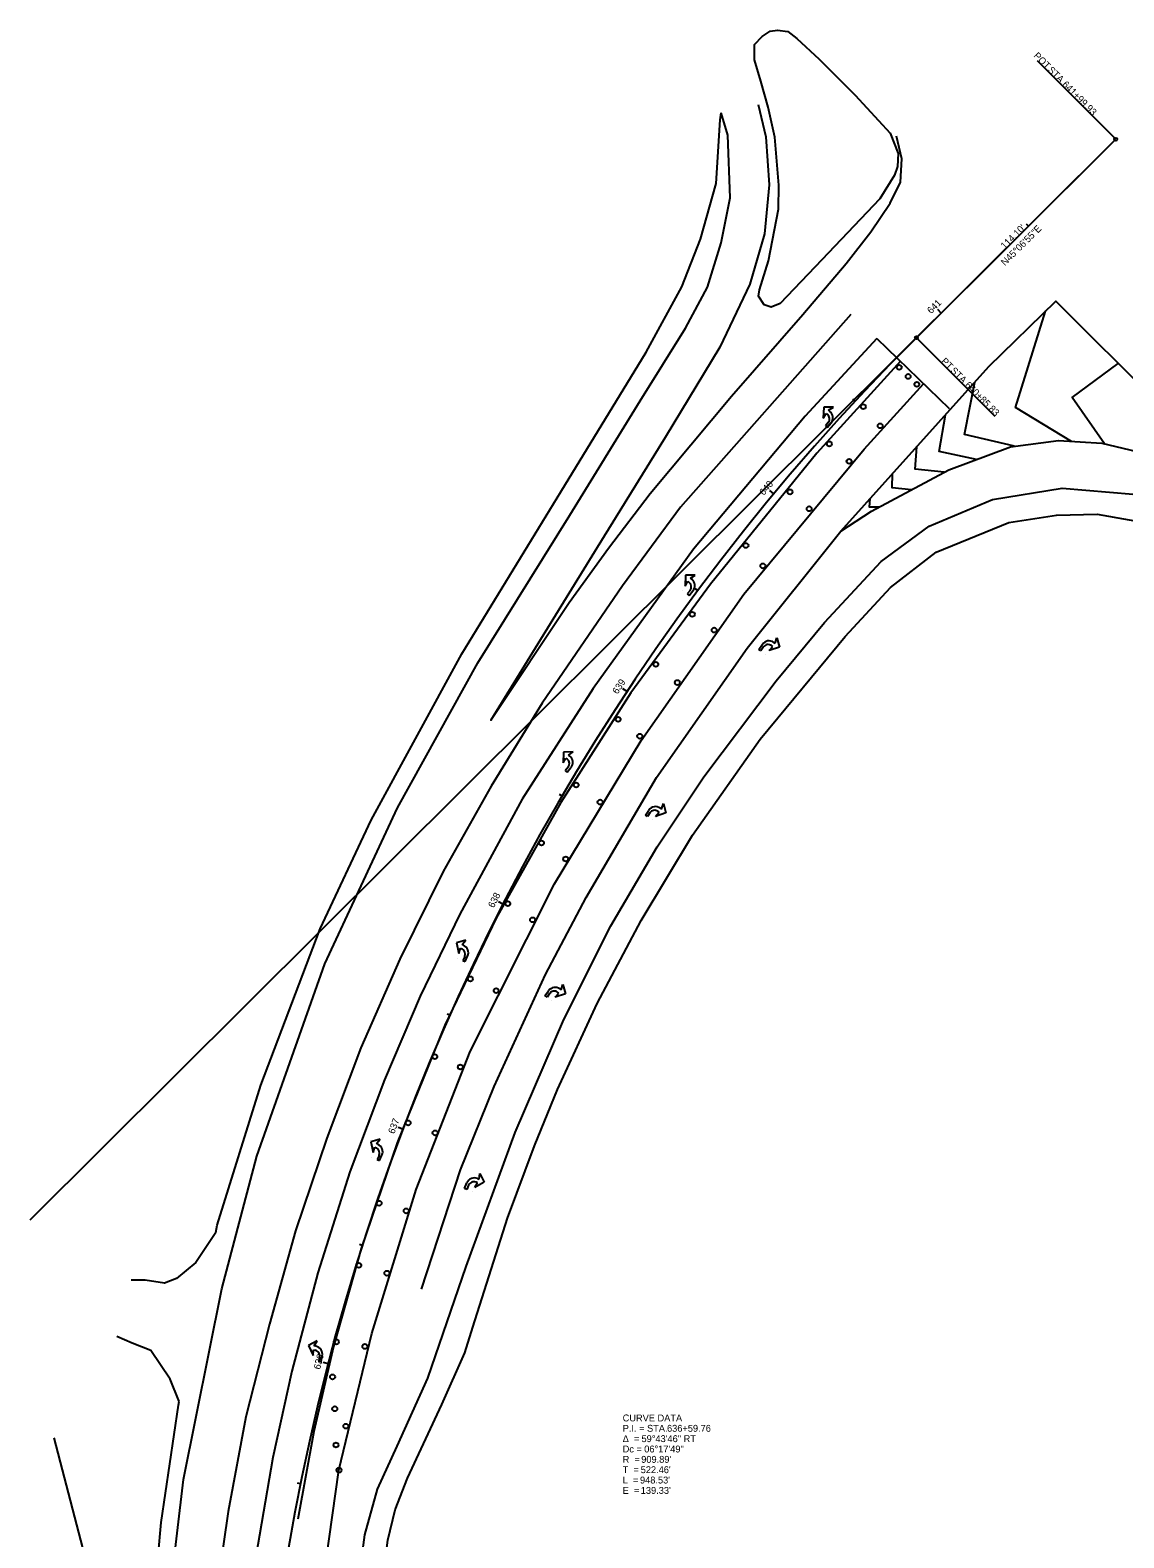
# Model space of a CAD drawing. Extents: x 171274 to 172251, y 454256 to 458569.
# Drawn here: x 171274 to 171718, y 456216 to 456829 of the extents above; entities that cross this region are included whole.
import ezdxf

# ---------------------------------------------------------------- set-up
doc = ezdxf.new("R2010")
doc.units = 0
for name, color, linetype in [('_CIVIL_CONSTRUCTION', 7, 'Continuous'), ('BR_P_Gen_Waterproofing', 7, 'Continuous'), ('BR_X_Beam_Hidden', 7, 'Continuous'), ('BR_X_Brg_Pad_Object', 7, 'Continuous'), ('BR_X_Gen_Approach_Slab', 7, 'Continuous'), ('BR_X_Rail_Object', 7, 'Continuous'), ('BR_X_Sub_Backwall', 7, 'Continuous'), ('PV_P_Saw_Cut_Line', 7, 'Continuous'), ('PV_X_Saw_Cut_Line', 7, 'Continuous'), ('PV_X_Walk', 7, 'Continuous'), ('SC_Scratch2', 7, 'Continuous'), ('SC_Scratch3', 7, 'Continuous'), ('SC_Scratch4', 7, 'Continuous'), ('UT_X_Water_Cells', 7, 'Continuous'), ('VG_X_Cells', 7, 'Continuous'), ('VG_X_Shrub_Line_Lt', 7, 'Continuous'), ('VG_X_Shrub_Line_Rt', 7, 'Continuous')]:
    doc.layers.add(name, color=color, linetype=linetype)

msp = doc.modelspace()

# ---------------------------------------------------------------- linework, layer by layer
at = {"layer": '_CIVIL_CONSTRUCTION'}
for p, q in [((171273.99, 456345.54), (171714.41, 456784.19)), ((171633.56, 456703.67), (171714.41, 456784.19)), ((171701.51, 454654.7), (171283.69, 456257.09))]:
    msp.add_line(p, q, dxfattribs=at)
msp.add_arc((172275.65, 456058.99), 909.89, 134.88472, 194.61425, dxfattribs=at)
msp.add_arc((172275.65, 456058.99), 909.89, 134.88472, 194.61425, dxfattribs=at)
at = {"layer": 'BR_X_Beam_Hidden'}
for points in [[(171569.33, 456798.27), (171572.44, 456785.16), (171573.8, 456765.69), (171571.94, 456745.78), (171566.04, 456725.39), (171553.76, 456699.87), (171531.66, 456663.16), (171504, 456618.55), (171460.9, 456548.38), (171492.68, 456596.2), (171508.69, 456618.21), (171525.54, 456640.38), (171558.59, 456679.98), (171587.53, 456713.13), (171605.13, 456733.84), (171615.03, 456746.64), (171622.89, 456758.28), (171627.16, 456766.82), (171627.64, 456776.24), (171625.47, 456785.54)], [(171602.92, 456625.18), (171663.01, 456692.03), (171690.1, 456718.51), (171772.11, 456636.73)], [(171627.06, 456694.1), (171593.23, 456656.78), (171550, 456603.64), (171517.74, 456559.5), (171489.28, 456515.03), (171463.11, 456468.03), (171442.22, 456424.53), (171422.9, 456376.79), (171408.32, 456333.98), (171397.11, 456294.2), (171389.07, 456259.62), (171382.57, 456224.06)], [(171432.73, 456317.37), (171448.55, 456365.88), (171462.25, 456399.72), (171483.02, 456445.22), (171499.61, 456476.41), (171528.05, 456525.13), (171564.96, 456577.65), (171602.92, 456625.18), (171615.36, 456633.22), (171646.74, 456650.07), (171671.8, 456659.37), (171691.22, 456661.9), (171708.76, 456660.87), (171728.62, 456656.06), (171746.7, 456650.15), (171767.78, 456639.28), (171772.11, 456636.73), (171794.37, 456614.66), (171830.07, 456578.67)]]:
    msp.add_lwpolyline(points, dxfattribs=at)
at = {"layer": 'BR_X_Brg_Pad_Object'}
for points in [[(171327.94, 456170.26), (171336.25, 456240.13), (171351.77, 456317.57), (171365.9, 456371.47), (171393.58, 456449.55), (171423.04, 456512.85), (171455.59, 456571.64), (171492.97, 456631.68), (171521.52, 456678.08), (171539.93, 456707.53), (171548.77, 456724.18), (171554.3, 456742.14), (171557.95, 456760.43), (171557.04, 456785.92), (171554.4, 456794.89)], [(171402.37, 456161.63), (171409.79, 456217.67), (171414.9, 456236.24), (171422.84, 456253.76), (171435.4, 456281.25), (171450.83, 456326.64), (171470.71, 456380.98), (171490.47, 456426.83), (171509.54, 456464.85), (171528.44, 456497.04), (171547.35, 456525.34), (171576.69, 456564.34), (171596.21, 456588.1), (171619.26, 456612.82), (171638.68, 456627.21), (171664.37, 456638), (171692.67, 456642.65), (171721.46, 456640.13), (171751.65, 456628.68), (171774.21, 456614.17), (171819.99, 456570.17)]]:
    msp.add_lwpolyline(points, dxfattribs=at)
at = {"layer": 'BR_X_Gen_Approach_Slab'}
msp.add_lwpolyline([(171617.49, 456703.32), (171588.41, 456671.87), (171543.08, 456617.86), (171502.42, 456561.24), (171473.6, 456516.31), (171448.38, 456469.66), (171432.22, 456436.4), (171417.81, 456402.4), (171403.7, 456365.07), (171390.74, 456323.99), (171380.22, 456284.08), (171372.41, 456249.06), (171365.59, 456208.9)], dxfattribs=at)
at = {"layer": 'BR_X_Rail_Object'}
for centre in [(171626.59, 456691.62), (171630.23, 456687.93), (171633.74, 456684.73), (171612, 456675.67), (171618.87, 456667.89), (171598.23, 456660.55), (171606.25, 456653.48), (171582.3, 456641.06), (171590.06, 456634.23), (171564.39, 456619.3), (171571.29, 456611.02), (171542.62, 456591.39), (171551.51, 456584.96), (171527.84, 456571.07), (171536.56, 456563.67), (171512.54, 456548.76), (171521.33, 456541.89), (171495.5, 456522.09), (171505.23, 456515.15), (171481.45, 456498.56), (171491.28, 456492.06), (171467.79, 456473.9), (171477.84, 456467.35), (171452.58, 456443.37), (171463.09, 456438.6), (171438.14, 456411.82), (171448.51, 456407.62), (171427.34, 456384.92), (171438.28, 456380.87), (171415.55, 456352.3), (171426.56, 456349.2), (171407.3, 456327.09), (171418.74, 456323.9), (171398.2, 456296.01), (171409.8, 456294.19), (171396.68, 456281.82), (171397.58, 456268.88), (171402.07, 456261.81), (171398.06, 456254.18), (171399.27, 456243.93)]:
    msp.add_circle(centre, 1, dxfattribs=at)
at = {"layer": 'BR_X_Sub_Backwall'}
msp.add_lwpolyline([(171399.27, 456243.93), (171412.62, 456299.43), (171430.57, 456357.84), (171452.53, 456413.92), (171486.74, 456481.97), (171521.83, 456540.12), (171563.53, 456599.56), (171612.4, 456658.42), (171636.48, 456684.91)], dxfattribs=at)
at = {"layer": 'PV_P_Saw_Cut_Line'}
msp.add_lwpolyline([(171624.65, 456769.69), (171618.76, 456760.02), (171595.18, 456735.32), (171578.31, 456717.51), (171574.63, 456716.11), (171571.85, 456717.07), (171569.46, 456720.5), (171569.93, 456723.14), (171573.55, 456734.86), (171577.66, 456755.81), (171577.69, 456765.63), (171576.16, 456785.11), (171573.37, 456797.29), (171570.45, 456807.76), (171567.85, 456816.44), (171567.93, 456822.67), (171570.95, 456825.94), (171574.17, 456828.08), (171577.25, 456828.51), (171581.38, 456827.94), (171585.04, 456825.14), (171594.17, 456816.74), (171608.72, 456802.09), (171622.85, 456786.66), (171626.11, 456778.44), (171625.91, 456773.15)], close=True, dxfattribs=at)
for points in [[(171349.3, 456340.43), (171349.93, 456343.34), (171367.6, 456400.19), (171391.6, 456463.7), (171412.29, 456507.8), (171449.08, 456575.38), (171489.26, 456641.12), (171523.9, 456697.76), (171538.43, 456724.37), (171545.99, 456743.73), (171552.35, 456766.31), (171553.97, 456792.06), (171554.4, 456794.89)], [(171478.59, 456375.6), (171487.98, 456398.43), (171504.03, 456433.44), (171521.95, 456467.05), (171542.72, 456501.75), (171570.11, 456540.74), (171604.7, 456582.33), (171622.99, 456602.24), (171641.52, 456616.62), (171671.01, 456628.7), (171690.37, 456631.59), (171706.84, 456631.97), (171730.61, 456627.89), (171744.29, 456622.3), (171760.51, 456613.41), (171776.5, 456599.81), (171809.32, 456567.8)], [(171461.92, 455723.14), (171461.11, 455726.64), (171445.31, 455796.47), (171431.02, 455865.63), (171421.47, 455918.95), (171413.26, 455981.96), (171409.27, 456040.86), (171408.32, 456093.56), (171412.13, 456160.37), (171419.13, 456215.58), (171422.03, 456227.81), (171427.08, 456240.66), (171441.08, 456270.63), (171450.32, 456291.63), (171453.6, 456301.97), (171467.65, 456346.3), (171478.59, 456375.6)], [(171558.29, 455107.46), (171557.48, 455110.64), (171540.93, 455172.92), (171510.71, 455286.81), (171486.61, 455378.45), (171470.46, 455441.39), (171454.22, 455507.71), (171429.71, 455601.02), (171414.88, 455651.31), (171387.7, 455745.41), (171360.93, 455847.8), (171341.64, 455927.77), (171327.71, 456008.91), (171320.5, 456092.02), (171319.84, 456141.55), (171327.18, 456222.76), (171334.15, 456270.38), (171334.45, 456271.77)]]:
    msp.add_lwpolyline(points, dxfattribs=at)
at = {"layer": 'PV_X_Saw_Cut_Line'}
for p, q in [((171599.89, 456675.51), (171595.94, 456675.42)), ((171597.96, 456674.19), (171599.89, 456675.51)), ((171599.89, 456675.51), (171599.89, 456675.51)), ((171595.94, 456675.42), (171595.79, 456671)), ((171595.79, 456671), (171596.95, 456672.95)), ((171596.95, 456672.95), (171597.49, 456672.51)), ((171598.47, 456673.77), (171597.96, 456674.19)), ((171594.83, 456669.3), (171594.83, 456669.3)), ((171597.82, 456669.27), (171596.64, 456667.83)), ((171596.64, 456667.83), (171597.42, 456667.2)), ((171597.42, 456667.2), (171598.98, 456669.12)), ((171539.85, 456607.24), (171539.69, 456602.83)), ((171539.69, 456602.83), (171540.85, 456604.78)), ((171543.79, 456607.33), (171539.85, 456607.24)), ((171540.85, 456604.78), (171541.4, 456604.33)), ((171541.86, 456606.02), (171543.79, 456607.33)), ((171542.38, 456605.6), (171541.86, 456606.02)), ((171543.79, 456607.33), (171543.79, 456607.33)), ((171538.74, 456601.13), (171538.74, 456601.13)), ((171541.73, 456601.1), (171540.55, 456599.66)), ((171540.55, 456599.66), (171541.32, 456599.03)), ((171541.32, 456599.03), (171542.89, 456600.95)), ((171569.66, 456577.15), (171571.07, 456579.19)), ((171571.54, 456578.11), (171570.48, 456576.58)), ((171573.76, 456576.64), (171575.31, 456578.29)), ((171577.96, 456578.01), (171573.76, 456576.64)), ((171575.31, 456578.29), (171574.74, 456578.69)), ((171575.68, 456579.98), (171576.23, 456579.6)), ((171576.23, 456579.6), (171576.96, 456581.82)), ((171576.96, 456581.82), (171576.96, 456581.82)), ((171576.96, 456581.82), (171577.96, 456578.01)), ((171570.48, 456576.58), (171569.66, 456577.15)), ((171572.4, 456575.25), (171572.4, 456575.25)), ((171490.38, 456535.47), (171490.23, 456531.06)), ((171494.33, 456535.56), (171490.38, 456535.47)), ((171492.39, 456534.24), (171494.33, 456535.56)), ((171494.33, 456535.56), (171494.33, 456535.56)), ((171489.27, 456529.36), (171489.27, 456529.36)), ((171490.23, 456531.06), (171491.38, 456533)), ((171492.26, 456529.33), (171491.08, 456527.88)), ((171491.38, 456533), (171491.93, 456532.56)), ((171491.86, 456527.25), (171493.42, 456529.17)), ((171492.91, 456533.82), (171492.39, 456534.24)), ((171491.08, 456527.88), (171491.86, 456527.25)), ((171523.59, 456509.87), (171525, 456511.9)), ((171525.47, 456510.83), (171524.41, 456509.3)), ((171527.7, 456509.36), (171529.25, 456511.01)), ((171531.89, 456510.73), (171527.7, 456509.36)), ((171529.25, 456511.01), (171528.67, 456511.41)), ((171529.61, 456512.7), (171530.16, 456512.32)), ((171530.16, 456512.32), (171530.89, 456514.54)), ((171530.89, 456514.54), (171530.89, 456514.54)), ((171530.89, 456514.54), (171531.89, 456510.73)), ((171524.41, 456509.3), (171523.59, 456509.87)), ((171526.33, 456507.97), (171526.33, 456507.97)), ((171450.79, 456459.07), (171446.99, 456458.01)), ((171446.99, 456458.01), (171447.93, 456453.69)), ((171447.93, 456453.69), (171448.57, 456455.86)), ((171448.57, 456455.86), (171449.2, 456455.57)), ((171449.24, 456457.31), (171450.79, 456459.07)), ((171449.85, 456457.03), (171449.24, 456457.31)), ((171450.79, 456459.07), (171450.79, 456459.07)), ((171447.42, 456451.81), (171447.42, 456451.81)), ((171450.32, 456452.52), (171449.54, 456450.83)), ((171449.54, 456450.83), (171450.44, 456450.41)), ((171450.44, 456450.41), (171451.49, 456452.65)), ((171482.87, 456436.48), (171484.28, 456438.51)), ((171484.75, 456437.44), (171483.69, 456435.91)), ((171486.97, 456435.96), (171488.52, 456437.62)), ((171491.17, 456437.34), (171486.97, 456435.96)), ((171488.52, 456437.62), (171487.95, 456438.02)), ((171488.89, 456439.31), (171489.44, 456438.93)), ((171489.44, 456438.93), (171490.16, 456441.15)), ((171490.16, 456441.15), (171490.16, 456441.15)), ((171490.16, 456441.15), (171491.17, 456437.34)), ((171483.69, 456435.91), (171482.87, 456436.48)), ((171485.61, 456434.58), (171485.61, 456434.58)), ((171416.03, 456378.25), (171412.23, 456377.19)), ((171412.23, 456377.19), (171413.17, 456372.88)), ((171414.48, 456376.5), (171416.03, 456378.25)), ((171415.09, 456376.22), (171414.48, 456376.5)), ((171416.03, 456378.25), (171416.03, 456378.25)), ((171412.66, 456371), (171412.66, 456371)), ((171413.17, 456372.88), (171413.81, 456375.05)), ((171413.81, 456375.05), (171414.45, 456374.75)), ((171415.56, 456371.7), (171414.78, 456370.01)), ((171414.78, 456370.01), (171415.69, 456369.59)), ((171415.69, 456369.59), (171416.73, 456371.84)), ((171456.15, 456362.06), (171456.39, 456364.39)), ((171456.39, 456364.39), (171456.39, 456364.39)), ((171456.39, 456364.39), (171458.19, 456360.88)), ((171450.27, 456358.25), (171451.21, 456360.54)), ((171451.19, 456357.87), (171450.27, 456358.25)), ((171451.9, 456359.59), (171451.19, 456357.87)), ((171458.19, 456360.88), (171454.39, 456358.64)), ((171454.39, 456358.64), (171455.55, 456360.58)), ((171455.55, 456360.58), (171454.9, 456360.85)), ((171455.54, 456362.32), (171456.15, 456362.06)), ((171453.35, 456356.99), (171453.35, 456356.99)), ((171390.38, 456296.43), (171386.92, 456294.53)), ((171389.27, 456294.37), (171390.38, 456296.43)), ((171390.38, 456296.43), (171390.38, 456296.43)), ((171386.92, 456294.53), (171388.82, 456290.54)), ((171388.82, 456290.54), (171388.95, 456292.8)), ((171388.95, 456292.8), (171389.64, 456292.66)), ((171389.93, 456294.24), (171389.27, 456294.37)), ((171391.42, 456289.95), (171391.05, 456288.12)), ((171392.02, 456287.92), (171392.53, 456290.35)), ((171388.76, 456288.59), (171388.76, 456288.59)), ((171391.05, 456288.12), (171392.02, 456287.92))]:
    msp.add_line(p, q, dxfattribs=at)
for centre, radius, start, end in [((171596.04, 456670.72), 2.3, 320.82278, 50.82278), ((171596.44, 456671.19), 3.28, 320.82278, 51.73127), ((171539.95, 456602.55), 2.3, 320.82278, 50.82278), ((171540.35, 456603.02), 3.28, 320.82278, 51.73127), ((171573.77, 456577.32), 3.28, 54.35147, 145.25996), ((171573.43, 456576.8), 2.3, 55.25996, 145.25996), ((171490.48, 456530.78), 2.3, 320.82278, 50.82278), ((171490.88, 456531.25), 3.28, 320.82278, 51.73127), ((171527.7, 456510.03), 3.28, 54.35147, 145.25996), ((171527.36, 456509.52), 2.3, 55.25996, 145.25996), ((171448.24, 456453.48), 2.3, 335.10444, 65.10444), ((171448.51, 456454.04), 3.28, 335.10444, 66.01293), ((171486.98, 456436.64), 3.28, 54.35147, 145.25996), ((171486.64, 456436.13), 2.3, 55.25996, 145.25996), ((171413.75, 456373.22), 3.28, 335.10444, 66.01293), ((171413.48, 456372.67), 2.3, 335.10444, 65.10444), ((171454.25, 456359.3), 3.28, 66.81072, 157.71921), ((171454.03, 456358.72), 2.3, 67.71921, 157.71921), ((171389.17, 456290.41), 2.3, 348.31748, 78.31748), ((171389.31, 456291.01), 3.28, 348.31748, 79.22597)]:
    msp.add_arc(centre, radius, start, end, dxfattribs=at)
at = {"layer": 'PV_X_Walk'}
for points in [[(171696.51, 456661.59), (171673.71, 456675.32), (171685.94, 456714.43)], [(171709.89, 456660.6), (171696.82, 456679.36), (171715.44, 456693.24)], [(171673.36, 456659.57), (171653.08, 456664.33), (171657.25, 456685.62)], [(171657.97, 456654.24), (171642.81, 456657.44), (171645.3, 456672.32)], [(171644.88, 456649.07), (171633.08, 456650.29), (171633.7, 456659.42)], [(171631.52, 456641.9), (171623.73, 456642.72), (171623.92, 456648.54)], [(171618.47, 456634.89), (171614.56, 456634.82), (171614.79, 456638.39)]]:
    msp.add_lwpolyline(points, dxfattribs=at)
at = {"layer": 'SC_Scratch2'}
for points in [[(171606.9, 456713.08), (171537.84, 456634.83), (171514.38, 456602.92), (171481.72, 456555.36), (171461.08, 456521.63), (171441.58, 456486.99), (171424.04, 456451.38), (171408.15, 456415.38), (171394.36, 456378.7), (171381.63, 456341.12), (171371.07, 456303.24), (171361.56, 456265.59), (171354.26, 456227.23), (171348.62, 456187.8), (171344.87, 456148.4), (171343.42, 456109.47), (171343.88, 456070.6), (171348.16, 456014.58), (171355.27, 455960.53), (171369.03, 455890.22), (171386.9, 455814.22), (171470.04, 455501.07), (171508.5, 455352.39)], [(171472.94, 455579.79), (171449.73, 455676.12), (171434.2, 455742.49), (171417.65, 455817.01), (171409.54, 455855.66), (171396.62, 455926.7), (171388.55, 455991.19), (171385.59, 456030.86), (171384.04, 456092.24), (171385.52, 456132), (171388.97, 456170.87), (171399.27, 456243.93), (171412.62, 456299.43), (171430.57, 456357.84), (171452.53, 456413.92), (171486.74, 456481.97), (171521.83, 456540.12), (171563.53, 456599.56), (171612.4, 456658.42), (171636.48, 456684.91)]]:
    msp.add_lwpolyline(points, dxfattribs=at)
at = {"layer": 'SC_Scratch3'}
msp.add_line((171617.49, 456703.32), (171646.92, 456674.96), dxfattribs=at)
at = {"layer": 'SC_Scratch4'}
for p, q in [((171714.41, 456784.19), (171682.65, 456816.07)), ((171633.56, 456703.67), (171665.32, 456671.78))]:
    msp.add_line(p, q, dxfattribs=at)
for centre in [(171714.41, 456784.19), (171633.56, 456703.67)]:
    msp.add_circle(centre, 0.6, dxfattribs=at)
at = {"layer": 'UT_X_Water_Cells'}
for points in [[(171349.3, 456340.43), (171341.18, 456328.25), (171333.43, 456321.75), (171328.52, 456319.8), (171320.66, 456321.11), (171314.99, 456321.12)], [(171334.45, 456271.77), (171330.85, 456280.93), (171323, 456292.46), (171315.33, 456295.46), (171309.14, 456298.19)]]:
    msp.add_lwpolyline(points, dxfattribs=at)
at = {"layer": 'VG_X_Shrub_Line_Lt'}
for p, q in [((171679.03, 456748.95), (171678.18, 456749.8)), ((171643.6, 456713.66), (171642.19, 456715.08)), ((171608.68, 456677.89), (171607.8, 456678.7)), ((171575.69, 456640.32), (171574.16, 456641.6)), ((171544.82, 456601), (171543.86, 456601.71)), ((171516.15, 456560.04), (171514.49, 456561.14)), ((171489.78, 456517.57), (171488.75, 456518.17)), ((171465.78, 456473.71), (171464, 456474.62)), ((171444.22, 456428.6), (171443.13, 456429.09)), ((171425.18, 456382.38), (171423.31, 456383.09)), ((171408.7, 456335.18), (171407.56, 456335.54)), ((171394.84, 456287.15), (171392.9, 456287.65)), ((171383.64, 456238.42), (171382.46, 456238.66))]:
    msp.add_line(p, q, dxfattribs=at)

# ---------------------------------------------------------------- texts
at = {"layer": 'BR_P_Gen_Waterproofing'}
msp.add_text('N45°06\'55"E', height=2.8, rotation=44.88472, dxfattribs=at).set_placement((171669.5, 456732.68))
at = {"layer": 'SC_Scratch4'}
for s, p in [('POT', (171680.89, 456817.89)), (' STA. ', (171685.92, 456812.84)), ('641+99.93', (171692.5, 456806.23)), ('PT', (171643.37, 456693.87)), (' STA. ', (171646.44, 456690.79)), ('640+85.83', (171653.02, 456684.19))]:
    msp.add_text(s, height=2.8, rotation=314.88472, dxfattribs=at).set_placement(p)
at = {"layer": 'VG_X_Cells'}
for s, p in [('CURVE DATA', (171514.39, 456263.74)), ('P.I. = STA. ', (171514.39, 456259.54)), ('636+59.76', (171532.38, 456259.54)), ('Δ  = ', (171514.39, 456255.34)), ('Dc = ', (171514.39, 456251.14)), ('59°43\'46" RT', (171522.03, 456255.34)), ('06°17\'49"', (171523.13, 456251.14)), ('R  = ', (171514.39, 456246.94)), ("909.89'", (171521.92, 456246.94)), ('T  = ', (171514.39, 456242.74)), ('L  = ', (171514.39, 456238.54)), ("948.53'", (171521.42, 456238.54)), ("522.46'", (171521.7, 456242.74)), ('E  = ', (171514.39, 456234.34)), ("139.33'", (171521.73, 456234.34))]:
    msp.add_text(s, height=2.8, dxfattribs=at).set_placement(p)
at = {"layer": 'VG_X_Shrub_Line_Lt'}
for s, rotation, p in [('641', 44.88472, (171639.55, 456713.16)), ('640', 50.28963, (171571.68, 456639.4)), ('639', 56.58666, (171512.29, 456558.72)), ('638', 62.88369, (171462.07, 456471.96)), ('637', 69.18072, (171421.69, 456380.24)), ('636', 75.47776, (171391.6, 456284.62))]:
    msp.add_text(s, height=2.8, rotation=rotation, dxfattribs=at).set_placement(p)
at = {"layer": 'VG_X_Shrub_Line_Rt'}
msp.add_text("114.10'", height=2.8, rotation=44.88472, dxfattribs=at).set_placement((171669.4, 456739.41))

doc.saveas('drawing.dxf')
